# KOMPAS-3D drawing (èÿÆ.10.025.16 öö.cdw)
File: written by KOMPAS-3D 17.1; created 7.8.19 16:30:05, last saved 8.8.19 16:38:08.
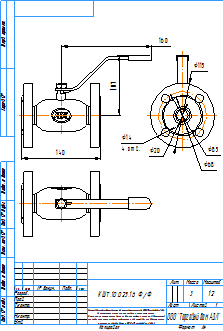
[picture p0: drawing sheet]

Sheet 1: A4, portrait

Title block, sheet 1: name: КШТ.10.025.16 Ф/Ф; material: Сталь 20  ГОСТ 1050-2013; mass: 3; sheets: 1; sheet format: A4; stored path: C:\Users\kka\KOMPAS_Work\Модели кранов для исследований\DN65\КШТ.10.065.16 СС.cdw

Views: Вид 1, Проекционный вид 2, Проекционный вид 3
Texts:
  kka
  adl
  Рама для чертежей
  Лит-Масса-Масштаб
  Материал-Предприятие
  Масштаб
  Изм.
  Лист
  № докум.
  Подп.
  Дата
  Лит.
  Разраб.
  Пров.
  Т.контр.
  Листов
  Внимание! Данный продукт является объектом авторского права ООО «Торговый Дом АДЛ».
  Запрещается изменение, копирование, распространение
  (в том числе путем копирования на другие сайты и ресурсы в Интернете)
  или любое иное использование информации и объектов без предварительного
  согласия правообладателя (ООО «Торговый Дом АДЛ»).
  Н.контр.
  Утв.
  ООО "Торговый дом АДЛ"
  Изменение
  Номер документа
  Подпись
  Обозначение документа
  Наименование изделия
  Масса изделия по ГОСТ 2.109-73
  Порядковый номер листа
  Общее количество листов в документе
  Характер работы, выполненной лицом, подписавшим документ
  Наименование или индекс предприятия, выпускающего документ
  Инв. № подл.
  Подп. и дата
  Взам. инв. №
  Инв. № дубл.
  Инвентарный номер подлинника по ГОСТ 2.501-68
  Подпись принявшего подлинник в отдел технической документации
  Инвентарный номер подлинника, взамен которого выпущен данный подлинник
  Инвентарный номер дубликата по ГОСТ 2.502-68
  Подпись принявшего дубликат в отдел технической документации
  Справ. №
  Перв. примен.
  Обозначение документа, взамен или на основании которого выпущен данный документ
  Обозначение документа, в котором впервые записан данный документ
  Подпись лица, копировавшего чертеж
  Обозначение формата листа
  !Рама для чертежа
Dimensions and other numbers on the sheet: 160; 107; 140; 20; 115; 85; 68; 14; 4 отв.; 1:2; 1; 3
